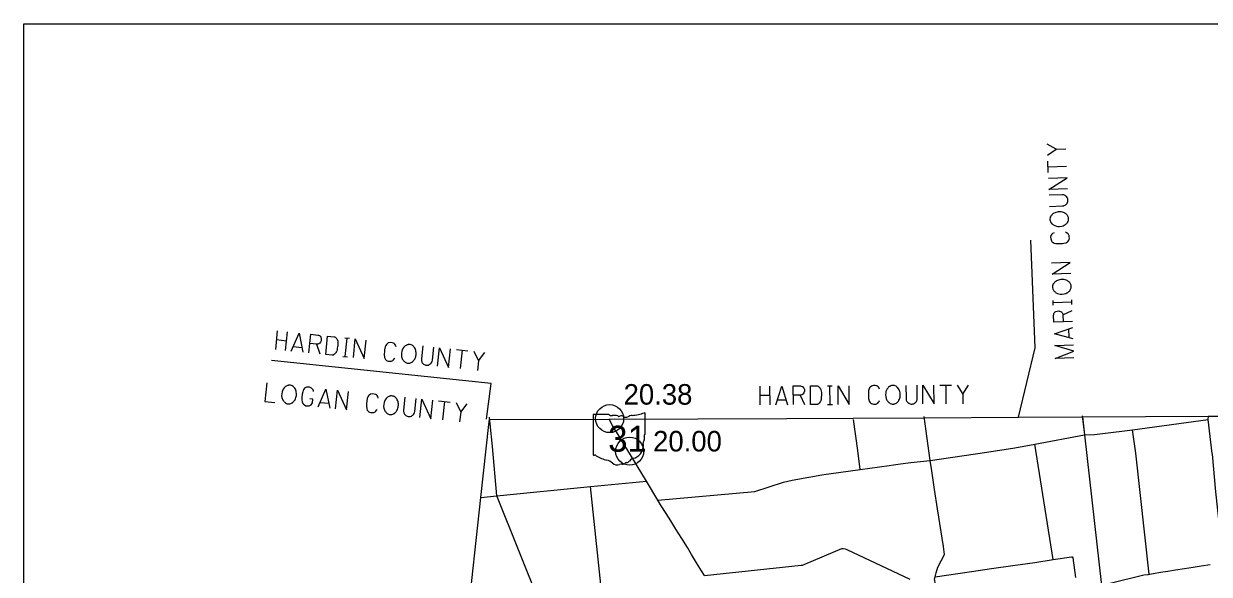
# Model space of a CAD drawing. Extents: x 1659811 to 1934326, y 644115 to 934867.
# Drawn here: x 1659811 to 1723269, y 905376 to 934867 of the extents above; entities that cross this region are included whole.
import ezdxf

# ---------------------------------------------------------------- set-up
doc = ezdxf.new("R2010")
doc.units = 0
for name, color, linetype in [('Default', 7, 'Continuous'), ('GM_X_Adjacent_County_Text', 7, 'Continuous'), ('GM_X_County', 7, 'Continuous'), ('GM_X_County_Road', 7, 'Continuous'), ('GM_X_State_Route', 7, 'Continuous'), ('GM_X_State_Shield', 7, 'Continuous'), ('GM_X_Township', 7, 'Continuous'), ('GM_X_Township_Road', 7, 'Continuous'), ('SC_Scratch1', 7, 'Continuous')]:
    doc.layers.add(name, color=color, linetype=linetype)

msp = doc.modelspace()

# ---------------------------------------------------------------- linework, layer by layer
at = {"layer": 'Default'}
for centre in [(1691171, 913713), (1692242, 911968)]:
    msp.add_circle(centre, 750, dxfattribs=at)
at = {"layer": 'GM_X_Adjacent_County_Text'}
for p, q in [((1715078, 928143), (1715597, 928163)), ((1714645, 926889), (1714621, 927511)), ((1714633, 927204), (1715632, 927242)), ((1713951, 917499), (1713717, 923273)), ((1714916, 919793), (1714907, 920044)), ((1715911, 919957), (1714911, 919918)), ((1715915, 919831), (1715906, 920083)), ((1715425, 919268), (1715928, 919508)), ((1673385, 918419), (1673281, 917424)), ((1673822, 917368), (1673925, 918363)), ((1715729, 918516), (1715747, 918052)), ((1673874, 917869), (1673334, 917926)), ((1675488, 917709), (1675654, 917177)), ((1676995, 918042), (1677246, 918016)), ((1677016, 917035), (1677120, 918029)), ((1674700, 917514), (1674238, 917562)), ((1676891, 917048), (1677142, 917022)), ((1682970, 917419), (1683588, 917354)), ((1683283, 917386), (1683179, 916391)), ((1713053, 913797), (1713951, 917499)), ((1684824, 915604), (1673075, 916830)), ((1684149, 916813), (1684095, 916296)), ((1684589, 913688), (1684824, 915604)), ((1699208, 915455), (1699213, 914455)), ((1699756, 914457), (1699751, 915457)), ((1702837, 915473), (1703089, 915475)), ((1702968, 914474), (1702963, 915474)), ((1708844, 915505), (1709466, 915508)), ((1709159, 915506), (1709165, 914506)), ((1676138, 914516), (1675676, 914564)), ((1682020, 914668), (1682638, 914603)), ((1682333, 914635), (1682229, 913641)), ((1699753, 914961), (1699210, 914958)), ((1700613, 914698), (1700149, 914696)), ((1701375, 914978), (1701598, 914467)), ((1702842, 914473), (1703094, 914475)), ((1710083, 915031), (1710086, 914511)), ((1683199, 914062), (1683145, 913545))]:
    msp.add_line(p, q, dxfattribs=at)
for points in [[(1714609, 927825), (1715078, 928143), (1714587, 928423)], [(1715679, 926023), (1714680, 925985), (1715656, 926613), (1714657, 926575)], [(1714714, 925080), (1715415, 925107), (1715485, 925117), (1715508, 925126), (1715547, 925143), (1715578, 925160), (1715609, 925185), (1715624, 925201), (1715631, 925209), (1715654, 925242), (1715669, 925266), (1715683, 925298), (1715697, 925346), (1715703, 925393), (1715701, 925440), (1715692, 925487), (1715682, 925519), (1715657, 925565), (1715632, 925603), (1715599, 925634), (1715559, 925664), (1715511, 925685), (1715471, 925700), (1715392, 925704), (1714691, 925678)], [(1714752, 924301), (1714761, 924278), (1714769, 924254), (1714795, 924216), (1714811, 924193), (1714844, 924155), (1714877, 924125), (1714893, 924109), (1714926, 924087), (1715006, 924051), (1715086, 924022), (1715157, 924009), (1715260, 924005), (1715370, 924017), (1715447, 924044), (1715509, 924070), (1715540, 924087), (1715579, 924112), (1715617, 924145), (1715639, 924169), (1715662, 924194), (1715685, 924226), (1715707, 924267), (1715735, 924339), (1715742, 924378), (1715739, 924457), (1715730, 924488), (1715721, 924519), (1715703, 924558), (1715678, 924596), (1715662, 924619), (1715645, 924642), (1715620, 924665), (1715588, 924688), (1715564, 924702), (1715540, 924717), (1715516, 924732), (1715467, 924754), (1715411, 924775), (1715348, 924789), (1715293, 924794), (1715285, 924794), (1715230, 924792), (1715182, 924790), (1715120, 924780), (1715057, 924762), (1715011, 924744), (1714957, 924719), (1714910, 924693), (1714865, 924652), (1714834, 924619), (1714804, 924587), (1714782, 924554), (1714760, 924506), (1714746, 924458), (1714740, 924411), (1714742, 924356), (1714752, 924301)], [(1714965, 923671), (1714880, 923628), (1714834, 923587), (1714804, 923547), (1714790, 923515), (1714777, 923427), (1714781, 923341), (1714816, 923232), (1714866, 923171), (1714907, 923141), (1714963, 923112), (1715050, 923091), (1715208, 923089), (1715326, 923094), (1715405, 923097), (1715475, 923107), (1715600, 923136), (1715623, 923145), (1715677, 923178), (1715715, 923211), (1715753, 923268), (1715767, 923316), (1715780, 923379), (1715777, 923450), (1715767, 923520), (1715758, 923544), (1715741, 923575), (1715708, 923605), (1715667, 923643), (1715619, 923672), (1715579, 923694)], [(1715852, 921491), (1714853, 921453), (1715829, 922081), (1714830, 922043)], [(1714890, 920674), (1714899, 920651), (1714908, 920627), (1714933, 920589), (1714950, 920566), (1714983, 920528), (1715015, 920498), (1715032, 920482), (1715064, 920460), (1715144, 920424), (1715224, 920395), (1715296, 920382), (1715398, 920378), (1715508, 920390), (1715586, 920417), (1715648, 920443), (1715679, 920460), (1715717, 920485), (1715755, 920518), (1715778, 920542), (1715801, 920567), (1715823, 920599), (1715845, 920640), (1715874, 920712), (1715880, 920751), (1715877, 920830), (1715868, 920861), (1715859, 920892), (1715842, 920931), (1715817, 920969), (1715800, 920992), (1715784, 921015), (1715759, 921038), (1715727, 921061), (1715702, 921075), (1715678, 921090), (1715654, 921105), (1715606, 921127), (1715550, 921148), (1715486, 921162), (1715431, 921168), (1715423, 921167), (1715368, 921165), (1715321, 921163), (1715258, 921153), (1715196, 921135), (1715149, 921117), (1715095, 921092), (1715049, 921066), (1715003, 921025), (1714973, 920992), (1714943, 920960), (1714920, 920927), (1714898, 920879), (1714884, 920831), (1714878, 920784), (1714880, 920729), (1714890, 920674)], [(1715950, 918918), (1714951, 918880), (1714937, 919258), (1714943, 919297), (1714957, 919353), (1714971, 919377), (1714986, 919401), (1715025, 919434), (1715063, 919459), (1715125, 919477), (1715220, 919481), (1715251, 919474), (1715299, 919461), (1715356, 919431), (1715380, 919401), (1715397, 919378), (1715405, 919362), (1715414, 919339), (1715425, 919268), (1715439, 918899)], [(1674135, 917335), (1674552, 918297), (1674753, 917271)], [(1715986, 917982), (1714975, 918258), (1715962, 918603)], [(1675067, 917238), (1675170, 918233), (1675546, 918193), (1675585, 918181), (1675638, 918160), (1675660, 918142), (1675682, 918124), (1675709, 918081), (1675728, 918040), (1675737, 917976), (1675727, 917882), (1675716, 917851), (1675696, 917806), (1675659, 917754), (1675625, 917734), (1675600, 917721), (1675583, 917714), (1675559, 917709), (1675488, 917709), (1675120, 917747)], [(1676079, 918138), (1676423, 918102), (1676454, 918091), (1676491, 918071), (1676513, 918053), (1676541, 918018), (1676562, 917992), (1676583, 917959), (1676620, 917860), (1676628, 917716), (1676617, 917607), (1676611, 917552), (1676596, 917482), (1676581, 917413), (1676566, 917343), (1676554, 917305), (1676525, 917252), (1676506, 917222), (1676444, 917165), (1676385, 917124), (1676368, 917118), (1676352, 917112), (1676320, 917107), (1675975, 917143), (1676079, 918138)], [(1677455, 916989), (1677559, 917983), (1678042, 916928), (1678146, 917922)], [(1679739, 917558), (1679709, 917648), (1679674, 917699), (1679638, 917735), (1679609, 917753), (1679524, 917778), (1679438, 917787), (1679325, 917767), (1679258, 917727), (1679222, 917691), (1679185, 917639), (1679153, 917556), (1679129, 917400), (1679116, 917282), (1679108, 917204), (1679109, 917133), (1679119, 917005), (1679124, 916981), (1679150, 916923), (1679177, 916880), (1679228, 916835), (1679273, 916815), (1679334, 916793), (1679405, 916785), (1679476, 916786), (1679500, 916791), (1679533, 916804), (1679568, 916832), (1679611, 916867), (1679647, 916910), (1679675, 916947)], [(1680393, 917680), (1680368, 917674), (1680344, 917669), (1680302, 917649), (1680277, 917636), (1680235, 917609), (1680200, 917581), (1680183, 917567), (1680156, 917538), (1680109, 917464), (1680069, 917389), (1680046, 917320), (1680028, 917219), (1680024, 917108), (1680040, 917028), (1680057, 916963), (1680069, 916930), (1680088, 916888), (1680116, 916846), (1680137, 916820), (1680158, 916794), (1680187, 916767), (1680223, 916739), (1680291, 916701), (1680329, 916689), (1680407, 916681), (1680439, 916685), (1680471, 916690), (1680512, 916701), (1680554, 916721), (1680579, 916734), (1680604, 916747), (1680630, 916768), (1680657, 916797), (1680675, 916819), (1680693, 916841), (1680711, 916863), (1680740, 916907), (1680769, 916960), (1680791, 917021), (1680805, 917075), (1680805, 917082), (1680811, 917137), (1680816, 917184), (1680815, 917248), (1680806, 917312), (1680795, 917361), (1680777, 917418), (1680758, 917467), (1680724, 917518), (1680696, 917553), (1680668, 917588), (1680639, 917614), (1680595, 917643), (1680549, 917663), (1680503, 917676), (1680448, 917682), (1680393, 917680)], [(1681169, 917607), (1681096, 916910), (1681097, 916838), (1681102, 916814), (1681114, 916773), (1681126, 916740), (1681146, 916706), (1681160, 916689), (1681167, 916681), (1681196, 916654), (1681218, 916636), (1681248, 916617), (1681293, 916596), (1681339, 916583), (1681386, 916579), (1681434, 916581), (1681466, 916586), (1681515, 916605), (1681557, 916624), (1681592, 916652), (1681627, 916688), (1681655, 916732), (1681675, 916770), (1681691, 916847), (1681764, 917545)], [(1716025, 916967), (1715026, 916929), (1716011, 917329), (1714998, 917637), (1715998, 917675)], [(1681966, 916518), (1682069, 917513), (1682553, 916457), (1682657, 917451)], [(1683902, 917321), (1684149, 916813), (1684497, 917259)], [(1672819, 915632), (1672715, 914637), (1673255, 914580)], [(1673985, 915502), (1673961, 915496), (1673936, 915491), (1673895, 915471), (1673870, 915458), (1673827, 915431), (1673793, 915403), (1673775, 915389), (1673749, 915360), (1673701, 915286), (1673662, 915211), (1673639, 915142), (1673620, 915041), (1673616, 914930), (1673632, 914850), (1673649, 914785), (1673661, 914752), (1673680, 914710), (1673708, 914668), (1673729, 914642), (1673750, 914616), (1673779, 914589), (1673815, 914561), (1673882, 914523), (1673921, 914511), (1673999, 914503), (1674031, 914507), (1674063, 914512), (1674104, 914523), (1674146, 914543), (1674171, 914556), (1674196, 914569), (1674222, 914590), (1674249, 914619), (1674267, 914641), (1674285, 914663), (1674303, 914684), (1674332, 914729), (1674361, 914781), (1674383, 914842), (1674397, 914896), (1674397, 914904), (1674403, 914959), (1674408, 915006), (1674407, 915069), (1674398, 915134), (1674387, 915182), (1674369, 915240), (1674351, 915289), (1674316, 915340), (1674288, 915375), (1674260, 915409), (1674231, 915436), (1674187, 915465), (1674142, 915485), (1674095, 915498), (1674041, 915504), (1673985, 915502)], [(1675328, 915171), (1675324, 915211), (1675305, 915253), (1675270, 915296), (1675220, 915348), (1675182, 915368), (1675152, 915379), (1675106, 915392), (1675012, 915402), (1674972, 915398), (1674947, 915393), (1674914, 915380), (1674847, 915340), (1674802, 915289), (1674772, 915229), (1674747, 915145), (1674718, 915021), (1674701, 914857), (1674695, 914723), (1674716, 914618), (1674753, 914519), (1674789, 914483), (1674833, 914447), (1674915, 914407), (1675002, 914398), (1675089, 914404), (1675122, 914417), (1675155, 914429), (1675190, 914457), (1675226, 914501), (1675265, 914568), (1675285, 914764), (1675121, 914781)], [(1675573, 914338), (1675990, 915300), (1676192, 914273)], [(1676505, 914240), (1676609, 915235), (1677092, 914179), (1677196, 915173)], [(1700071, 914459), (1700381, 915461), (1700693, 914462)], [(1701008, 914464), (1701003, 915464), (1701381, 915466), (1701420, 915458), (1701475, 915443), (1701499, 915427), (1701523, 915411), (1701554, 915372), (1701578, 915333), (1701594, 915270), (1701595, 915176), (1701587, 915144), (1701572, 915097), (1701540, 915041), (1701509, 915018), (1701485, 915002), (1701470, 914994), (1701446, 914986), (1701375, 914978), (1701005, 914976)], [(1701916, 915469), (1702262, 915470), (1702294, 915463), (1702333, 915447), (1702357, 915432), (1702389, 915400), (1702412, 915377), (1702436, 915345), (1702484, 915251), (1702508, 915109), (1702509, 914999), (1702509, 914944), (1702502, 914873), (1702494, 914802), (1702487, 914731), (1702479, 914692), (1702456, 914637), (1702440, 914605), (1702385, 914542), (1702331, 914494), (1702315, 914486), (1702299, 914478), (1702268, 914470), (1701921, 914469), (1701916, 915469)], [(1703409, 914476), (1703404, 915476), (1704000, 914479), (1703994, 915479)], [(1705617, 915291), (1705578, 915377), (1705538, 915424), (1705498, 915456), (1705467, 915471), (1705380, 915487), (1705294, 915486), (1705183, 915454), (1705121, 915406), (1705089, 915367), (1705058, 915312), (1705035, 915225), (1705028, 915067), (1705029, 914949), (1705029, 914871), (1705037, 914800), (1705062, 914674), (1705069, 914650), (1705101, 914595), (1705133, 914556), (1705188, 914517), (1705236, 914502), (1705299, 914486), (1705370, 914487), (1705440, 914495), (1705464, 914503), (1705495, 914519), (1705527, 914550), (1705566, 914590), (1705597, 914637), (1705620, 914677)], [(1706254, 915483), (1706230, 915475), (1706207, 915467), (1706168, 915443), (1706144, 915428), (1706105, 915396), (1706074, 915364), (1706058, 915348), (1706035, 915317), (1705996, 915238), (1705964, 915159), (1705949, 915088), (1705942, 914986), (1705950, 914875), (1705974, 914797), (1705998, 914734), (1706014, 914702), (1706038, 914663), (1706070, 914624), (1706093, 914601), (1706117, 914577), (1706149, 914554), (1706188, 914530), (1706259, 914499), (1706299, 914491), (1706377, 914492), (1706409, 914500), (1706440, 914508), (1706480, 914524), (1706519, 914548), (1706542, 914564), (1706566, 914579), (1706589, 914603), (1706613, 914635), (1706628, 914658), (1706644, 914682), (1706660, 914706), (1706683, 914753), (1706706, 914809), (1706722, 914872), (1706729, 914927), (1706729, 914935), (1706729, 914990), (1706729, 915037), (1706721, 915100), (1706705, 915163), (1706689, 915210), (1706665, 915265), (1706641, 915312), (1706601, 915359), (1706570, 915390), (1706538, 915422), (1706506, 915445), (1706459, 915469), (1706412, 915484), (1706364, 915492), (1706309, 915492), (1706254, 915483)], [(1707034, 915495), (1707037, 914794), (1707045, 914724), (1707053, 914700), (1707069, 914661), (1707085, 914629), (1707109, 914598), (1707125, 914582), (1707133, 914575), (1707165, 914551), (1707188, 914535), (1707220, 914520), (1707267, 914504), (1707314, 914497), (1707362, 914497), (1707409, 914505), (1707440, 914513), (1707487, 914537), (1707527, 914561), (1707558, 914592), (1707589, 914632), (1707613, 914679), (1707628, 914719), (1707636, 914798), (1707632, 915498)], [(1707944, 914500), (1707939, 915500), (1708535, 914503), (1708529, 915503)], [(1709781, 915510), (1710083, 915031), (1710380, 915513)], [(1678789, 914809), (1678759, 914899), (1678724, 914950), (1678689, 914985), (1678659, 915004), (1678574, 915029), (1678488, 915038), (1678375, 915018), (1678308, 914978), (1678272, 914942), (1678235, 914890), (1678203, 914807), (1678179, 914651), (1678166, 914533), (1678158, 914455), (1678158, 914384), (1678169, 914256), (1678174, 914232), (1678200, 914174), (1678227, 914131), (1678278, 914086), (1678323, 914066), (1678384, 914043), (1678455, 914036), (1678526, 914036), (1678550, 914042), (1678583, 914054), (1678618, 914082), (1678661, 914117), (1678697, 914161), (1678725, 914198)], [(1679443, 914930), (1679418, 914925), (1679394, 914919), (1679353, 914900), (1679327, 914887), (1679285, 914859), (1679250, 914831), (1679233, 914817), (1679206, 914789), (1679159, 914714), (1679119, 914639), (1679096, 914571), (1679078, 914469), (1679074, 914359), (1679090, 914278), (1679106, 914213), (1679119, 914180), (1679138, 914139), (1679166, 914096), (1679186, 914070), (1679208, 914044), (1679236, 914018), (1679273, 913990), (1679340, 913951), (1679379, 913939), (1679457, 913931), (1679489, 913936), (1679521, 913940), (1679562, 913952), (1679604, 913971), (1679629, 913984), (1679654, 913997), (1679680, 914019), (1679707, 914047), (1679725, 914069), (1679743, 914091), (1679761, 914113), (1679789, 914157), (1679819, 914210), (1679841, 914271), (1679854, 914325), (1679855, 914333), (1679861, 914387), (1679866, 914434), (1679865, 914498), (1679855, 914562), (1679845, 914611), (1679827, 914668), (1679808, 914718), (1679774, 914769), (1679746, 914803), (1679718, 914838), (1679689, 914865), (1679645, 914893), (1679599, 914914), (1679553, 914926), (1679498, 914932), (1679443, 914930)], [(1680219, 914857), (1680146, 914160), (1680146, 914088), (1680152, 914064), (1680163, 914023), (1680176, 913990), (1680196, 913957), (1680210, 913939), (1680217, 913931), (1680246, 913904), (1680268, 913886), (1680297, 913867), (1680343, 913846), (1680389, 913834), (1680436, 913829), (1680484, 913831), (1680516, 913836), (1680565, 913855), (1680607, 913874), (1680641, 913902), (1680677, 913938), (1680705, 913982), (1680725, 914020), (1680741, 914097), (1680814, 914794)], [(1681015, 913768), (1681119, 914762), (1681603, 913706), (1681707, 914701)], [(1682952, 914571), (1683199, 914062), (1683547, 914508)]]:
    msp.add_lwpolyline(points, dxfattribs=at)
at = {"layer": 'GM_X_County'}
msp.add_lwpolyline([(1683546, 902749), (1684285, 909495), (1684713, 913407), (1684743, 913679), (1684770, 913678), (1690379, 913673), (1691130, 913677), (1700650, 913725), (1704212, 913742), (1707999, 913760), (1713053, 913797), (1716496, 913811), (1723205, 913838), (1725148, 913846)], dxfattribs=at)
at = {"layer": 'GM_X_County_Road'}
for points in [[(1709105, 900768), (1709006, 901591), (1708912, 902357), (1708832, 903084), (1708800, 903417), (1708743, 903896), (1708674, 904398), (1708607, 904841), (1708566, 905132), (1708597, 905240), (1708654, 905453), (1708741, 905767), (1709091, 906432), (1709039, 906871), (1708726, 908885), (1708567, 909924), (1708418, 910925), (1708334, 911466), (1708006, 913831)], [(1724026, 906020), (1723624, 909802), (1723436, 911803), (1723431, 911843), (1723214, 913667), (1723218, 913847)], [(1684714, 913426), (1684781, 913433)], [(1687482, 903699), (1685143, 909580), (1684907, 912222), (1684781, 913433), (1684740, 913792)], [(1716581, 912838), (1716608, 912843), (1717121, 912864), (1717561, 912911), (1718595, 913042), (1719163, 913111), (1723214, 913667)], [(1708334, 911466), (1711369, 911916), (1712858, 912152), (1713923, 912340), (1716581, 912838)], [(1720049, 905383), (1719329, 911869), (1719163, 913111)], [(1714906, 906161), (1713923, 912340)], [(1693760, 909347), (1698939, 909819), (1700484, 910306), (1700950, 910415), (1701828, 910587), (1702529, 910709), (1702765, 910732), (1702901, 910755), (1704585, 910992), (1706135, 911205), (1706373, 911238), (1706746, 911288), (1707296, 911356), (1708334, 911466)], [(1684285, 909495), (1685143, 909580), (1690144, 910073), (1693150, 910359)], [(1692320, 890154), (1691562, 897616), (1690919, 903414), (1690917, 903448), (1690907, 903477), (1690822, 903676), (1690812, 903710), (1690801, 903808), (1690144, 910073)], [(1696246, 905320), (1701427, 905860), (1701487, 905873), (1701619, 905916), (1703603, 906752), (1703673, 906765), (1703776, 906744), (1703861, 906711), (1707236, 905111)], [(1708597, 905240), (1710549, 905528), (1711618, 905682), (1712745, 905843), (1713924, 906014), (1714906, 906161), (1715887, 906312), (1715937, 906305), (1715963, 906253), (1716115, 905212)]]:
    msp.add_lwpolyline(points, dxfattribs=at)
at = {"layer": 'GM_X_State_Route'}
for points in [[(1691488, 913082), (1691324, 913349), (1691141, 913692)], [(1696246, 905320), (1696091, 905570), (1695830, 905997), (1695561, 906437), (1695335, 906806), (1695035, 907287), (1694715, 907796), (1694444, 908236), (1694196, 908626), (1693931, 909051), (1693760, 909347), (1693150, 910359), (1692096, 912105), (1691928, 912349), (1691731, 912678), (1691535, 913005), (1691490, 913078), (1691488, 913082)], [(1715520, 904071), (1715607, 904114), (1715803, 904220), (1716003, 904295), (1717405, 904743), (1717525, 904776), (1717737, 904834), (1717965, 904895), (1719759, 905350), (1720000, 905370), (1720049, 905383), (1720063, 905386), (1720291, 905422), (1720664, 905482), (1721050, 905544), (1721469, 905610), (1721937, 905686), (1722402, 905759), (1722836, 905826), (1723307, 905902)]]:
    msp.add_lwpolyline(points, dxfattribs=at)
at = {"layer": 'GM_X_State_Shield'}
for p, q in [((1690284, 913906), (1690284, 911792)), ((1691127, 913942), (1690311, 913942)), ((1693068, 912889), (1693068, 913994)), ((1693068, 912889), (1693068, 912889))]:
    msp.add_line(p, q, dxfattribs=at)
for centre, radius, start, end in [((1690316, 913910), 32.3, 98.1301, 188.1301), ((1691321, 914187), 313, 231.61951, 271.11188), ((1691424, 912756), 1123, 80.48669, 94.98827), ((1691679, 913921), 90.3, 219.79206, 297.10237), ((1691812, 913677), 188, 54.46668, 119.14113), ((1692054, 914012), 226, 233.85621, 294.82819), ((1692453, 913297), 594, 97.34618, 120.76885), ((1692076, 916823), 2953, 275.84447, 288.90645), ((1693037, 913999), 31, 351.86209, 97.738), ((1693179, 912426), 210, 136.8065, 186.92959), ((1693061, 912808), 48, 107.94398, 210.33697), ((1692756, 912668), 288, 340.03296, 23.64957), ((1693035, 912885), 33.2, 289.60381, 7.73413), ((1692242, 912286), 739, 292.30889, 8.98584), ((1690316, 911788), 32.5, 171.95839, 258.30661), ((1690321, 912004), 248, 267.33899, 280.60386), ((1690372, 911670), 89.5, 29.74838, 93.27175), ((1691502, 913569), 2132, 240.41292, 257.1985), ((1690867, 910843), 667, 47.18416, 75.83597), ((1691588, 911660), 423, 230.70037, 286.29184), ((1691833, 910929), 348, 85.69512, 111.20995), ((1691864, 911502), 226, 268.77702, 315.54927), ((1692068, 911297), 63.5, 65.75173, 132.64842), ((1692041, 911588), 239, 282.87319, 323.27711), ((1692553, 911199), 404, 94.40312, 142.57675)]:
    msp.add_arc(centre, radius, start, end, dxfattribs=at)
at = {"layer": 'GM_X_Township'}
msp.add_lwpolyline([(1718862, 893030), (1718172, 899094), (1718095, 899767), (1717525, 904776), (1716608, 912843), (1716496, 913811)], dxfattribs=at)
at = {"layer": 'GM_X_Township_Road'}
for points in [[(1716608, 912843), (1716475, 913871)], [(1704585, 910992), (1704450, 912009), (1704224, 913664)]]:
    msp.add_lwpolyline(points, dxfattribs=at)
at = {"layer": 'SC_Scratch1'}
msp.add_lwpolyline([(1659811, 738617), (1659811, 934867), (1794311, 934867), (1794311, 738617)], close=True, dxfattribs=at)

# ---------------------------------------------------------------- texts
at = {"layer": 'Default'}
for s, p in [('20.38', (1691921, 914463)), ('20.00', (1693499, 911956))]:
    msp.add_text(s, height=1100, dxfattribs=at).set_placement(p)
at = {"layer": 'GM_X_State_Shield'}
msp.add_text('31', height=1392.2, dxfattribs=at).set_placement((1691094, 911941))

doc.saveas('drawing.dxf')
